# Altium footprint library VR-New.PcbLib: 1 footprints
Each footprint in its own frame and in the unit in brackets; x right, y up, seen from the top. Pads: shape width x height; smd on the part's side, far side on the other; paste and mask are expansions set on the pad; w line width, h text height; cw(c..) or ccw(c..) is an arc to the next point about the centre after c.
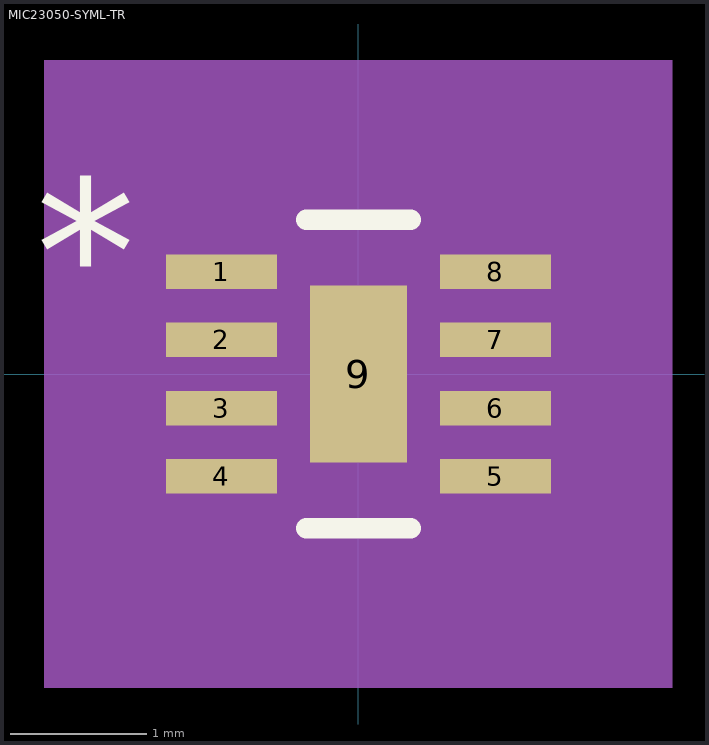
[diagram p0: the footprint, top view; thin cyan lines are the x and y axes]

## MIC23050-SYML-TR [mil]
pads (9):
  rect 32x10 smd paste+0 mask+0: 1(-39.5,29.53) 2(-39.5,9.84) 3(-39.5,-9.84) 4(-39.5,-29.53) 5(39.5,-29.53) 6(39.5,-9.84) 7(39.5,9.84) 8(39.5,29.53)
  rect 28x51 smd paste+0 mask+0: 9(0,0)
Top Overlay:
  lines w6: -15.01,-44.5 15.01,-44.5 ; -15.01,44.5 15.01,44.5
  text "*" at -93,14.37 h50
Mechanical 5:
  region: 90.5,-90.5 -90.5,-90.5 -90.5,90.5 90.5,90.5
Mechanical 13:
  lines w1: -39.5,-10.5 10.5,39.5 ; -39.5,-39.5 39.5,-39.5 39.5,39.5 -39.5,39.5 -39.5,-39.5 ; -39.5,-35.53 -39.5,-23.53 -39.5,-35.53 ; -39.5,-15.84 -39.5,-3.84 -39.5,-15.84 ; -39.5,3.84 -39.5,15.84 -39.5,3.84 ; -39.5,23.53 -39.5,35.53 -39.5,23.53 ; 39.5,-35.53 39.5,-23.53 39.5,-35.53 ; 39.5,-15.84 39.5,-3.84 39.5,-15.84 ; 39.5,3.84 39.5,15.84 39.5,3.84 ; 39.5,23.53 39.5,35.53 39.5,23.53
  text "*" at -36,14.37 h50
Mechanical 15:
  region: -15.16,-59.5 -59.5,-59.5 -59.5,-54.53 -75.5,-54.53 -75.5,54.53 -59.5,54.53 -59.5,59.5 -15.16,59.5 -15.16,75.5 15.16,75.5 15.16,59.5 59.5,59.5 59.5,54.53 75.5,54.53 75.5,-54.53 59.5,-54.53 59.5,-59.5 15.16,-59.5 15.16,-75.5 -15.16,-75.5
  lines w6: -75.5,-54.53 -59.5,-54.53 -59.5,-59.5 -15.16,-59.5 -15.16,-75.5 15.16,-75.5 15.16,-59.5 59.5,-59.5 59.5,-54.53 75.5,-54.53 75.5,54.53 59.5,54.53 59.5,59.5 15.16,59.5 15.16,75.5 -15.16,75.5 -15.16,59.5 -59.5,59.5 -59.5,54.53 -75.5,54.53 -75.5,-54.53
3D body: height 10, standoff 0, extent 0,0 10,10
